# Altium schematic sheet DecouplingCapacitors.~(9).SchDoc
size A4
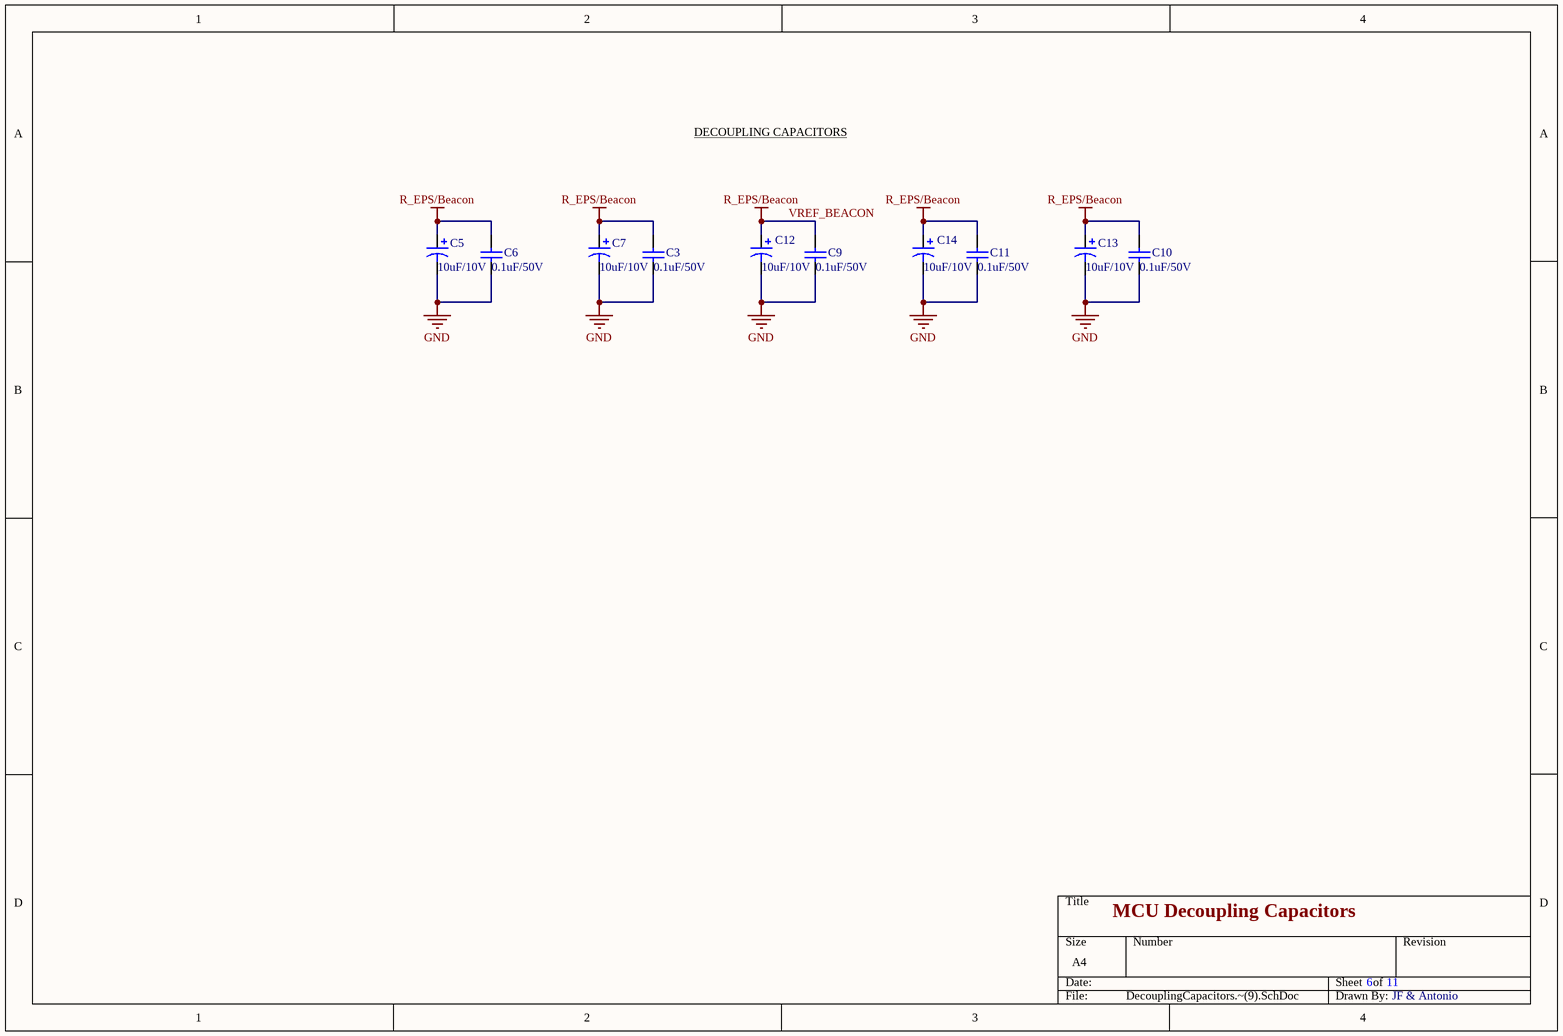
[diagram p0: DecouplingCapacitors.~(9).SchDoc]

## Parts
C3  value 0.1uF/50V  [C1206]
C5  value 10uF/10V  [C0805]
C6  value 0.1uF/50V  [C1206]
C7  value 10uF/10V  [C0805]
C9  value 0.1uF/50V  [C1206]
C10  value 0.1uF/50V  [C1206]
C11  value 0.1uF/50V  [C1206]
C12  value 10uF/10V  [C0805]
C13  value 10uF/10V  [C0805]
C14  value 10uF/10V  [C0805]

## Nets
GND: C3.2 C5.2 C6.2 C7.2 C9.2 C10.2 C11.2 C12.2 C13.2 C14.2
VREF_BEACON: C3.1 C5.1 C6.1 C7.1 C9.1 C10.1 C11.1 C12.1 C13.1 C14.1  [also labelled R_EPS/Beacon]

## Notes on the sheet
- DECOUPLING CAPACITORS
- MCU Decoupling Capacitors
- 6
- 11
- JF & Antonio

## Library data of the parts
C3 C6 C9-C11 = Cap Semi: Capacitor (Semiconductor SIM Model)
C5 C7 C12-C14 = Cap Pol3: Polarized Capacitor (Surface Mount)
